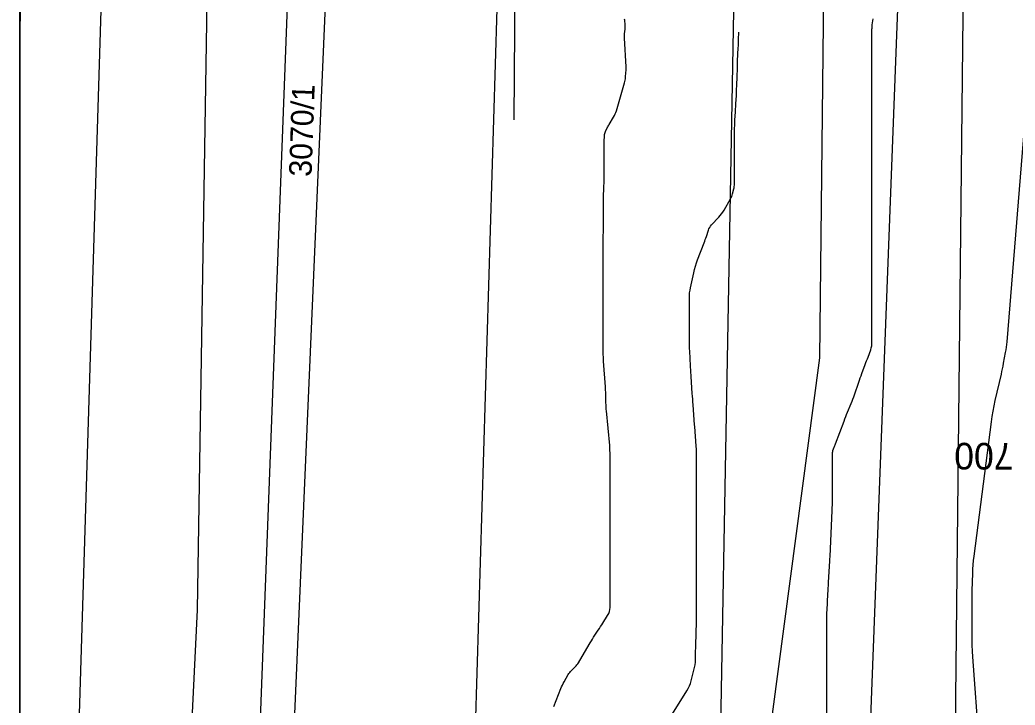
# Model space of a CAD drawing. Extents: x -534410 to -534262, y -1190162 to -1189584.
# Drawn here: x -534410.13 to -534372.72, y -1189890.36 to -1189864.58 of the extents above; entities that cross this region are included whole.
import ezdxf

# ---------------------------------------------------------------- set-up
doc = ezdxf.new("R2010")
doc.units = 0
for name, color, linetype in [('30', 7, 'Continuous'), ('31', 7, 'Continuous'), ('_N_text', 7, 'Continuous'), ('_rámeček', 7, 'Continuous'), ('_rámeček_mřížka', 7, 'Continuous'), ('Hranice parcel', 7, 'Continuous'), ('Parcelní čísla', 7, 'Continuous')]:
    doc.layers.add(name, color=color, linetype=linetype)

msp = doc.modelspace()

# ---------------------------------------------------------------- linework, layer by layer
at = {"layer": '30'}
for points in [[(-534390.792, -1189830.764), (-534391.145, -1189834.263), (-534391.226, -1189835.167), (-534391.285, -1189836.071), (-534391.324, -1189836.977), (-534391.341, -1189837.885), (-534391.562, -1189868.34)], [(-534374.066, -1189891.779), (-534374.31, -1189888.535), (-534374.324, -1189888.32), (-534374.334, -1189888.104), (-534374.339, -1189887.887), (-534374.341, -1189887.671), (-534374.338, -1189886.697), (-534374.337, -1189886.535), (-534374.335, -1189886.373), (-534374.332, -1189886.21), (-534374.329, -1189886.048), (-534374.312, -1189885.399), (-534374.306, -1189885.237), (-534374.295, -1189885.075), (-534374.281, -1189884.913), (-534374.262, -1189884.752), (-534373.614, -1189879.703), (-534373.585, -1189879.5), (-534373.551, -1189879.298), (-534373.513, -1189879.097), (-534373.469, -1189878.897), (-534373.238, -1189877.899), (-534373.215, -1189877.799), (-534373.194, -1189877.698), (-534373.173, -1189877.598), (-534373.153, -1189877.497), (-534373.077, -1189877.095), (-534373.059, -1189876.994), (-534373.044, -1189876.892), (-534373.032, -1189876.791), (-534373.022, -1189876.689), (-534371.559, -1189858.553)], [(-534385.597, -1189890.68), (-534385.058, -1189889.813), (-534385.007, -1189889.724), (-534384.963, -1189889.632), (-534384.926, -1189889.538), (-534384.896, -1189889.44), (-534384.791, -1189889.043), (-534384.767, -1189888.943), (-534384.75, -1189888.843), (-534384.738, -1189888.741), (-534384.733, -1189888.639), (-534384.715, -1189887.888), (-534384.714, -1189887.866), (-534384.714, -1189887.823), (-534384.714, -1189887.801), (-534384.698, -1189887.082), (-534384.695, -1189886.963), (-534384.693, -1189886.844), (-534384.692, -1189886.726), (-534384.692, -1189886.607), (-534384.692, -1189881.082), (-534384.693, -1189880.963), (-534384.696, -1189880.845), (-534384.702, -1189880.726), (-534384.71, -1189880.608), (-534384.764, -1189879.872), (-534384.769, -1189879.808), (-534384.824, -1189879.057), (-534384.832, -1189878.951), (-534384.839, -1189878.844), (-534384.847, -1189878.738), (-534384.853, -1189878.632), (-534384.893, -1189877.994), (-534384.917, -1189877.596), (-534384.952, -1189877.039), (-534384.957, -1189876.942), (-534384.961, -1189876.844), (-534384.963, -1189876.747), (-534384.964, -1189876.65), (-534384.964, -1189876.12), (-534384.964, -1189875.955), (-534384.964, -1189875.624), (-534384.964, -1189875.514), (-534384.964, -1189875.039), (-534384.961, -1189874.942), (-534384.953, -1189874.846), (-534384.94, -1189874.75), (-534384.922, -1189874.654), (-534384.801, -1189874.092), (-534384.772, -1189873.967), (-534384.737, -1189873.844), (-534384.698, -1189873.722), (-534384.655, -1189873.601), (-534384.407, -1189872.959), (-534384.386, -1189872.902), (-534384.365, -1189872.844), (-534384.345, -1189872.786), (-534384.325, -1189872.727), (-534384.25, -1189872.493), (-534384.228, -1189872.436), (-534384.2, -1189872.382), (-534384.167, -1189872.332), (-534384.127, -1189872.286), (-534383.86, -1189872.004), (-534383.804, -1189871.941), (-534383.751, -1189871.874), (-534383.703, -1189871.805), (-534383.659, -1189871.732), (-534383.416, -1189871.304), (-534383.393, -1189871.261), (-534383.374, -1189871.217), (-534383.357, -1189871.172), (-534383.344, -1189871.126), (-534383.296, -1189870.938), (-534383.285, -1189870.891), (-534383.278, -1189870.844), (-534383.273, -1189870.796), (-534383.272, -1189870.748), (-534383.272, -1189868.967), (-534383.271, -1189868.906), (-534383.271, -1189868.845), (-534383.269, -1189868.783), (-534383.267, -1189868.722), (-534383.259, -1189868.478), (-534383.257, -1189868.417), (-534383.254, -1189868.356), (-534383.251, -1189868.295), (-534383.247, -1189868.234), (-534383.2, -1189867.534), (-534383.196, -1189867.465), (-534383.192, -1189867.396), (-534383.189, -1189867.327), (-534383.187, -1189867.258), (-534383.178, -1189866.983), (-534383.176, -1189866.913), (-534383.173, -1189866.844), (-534383.171, -1189866.775), (-534383.17, -1189866.706), (-534383.161, -1189866.405), (-534383.159, -1189866.332), (-534383.157, -1189866.259), (-534383.153, -1189866.186), (-534383.15, -1189866.113), (-534383.124, -1189865.628), (-534383.12, -1189865.55), (-534383.117, -1189865.471), (-534383.114, -1189865.393), (-534383.112, -1189865.315), (-534383.105, -1189865.034)]]:
    msp.add_lwpolyline(points, dxfattribs=at)
at = {"layer": '31'}
for points in [[(-534390.056, -1189890.413), (-534389.793, -1189889.733), (-534389.767, -1189889.668), (-534389.738, -1189889.605), (-534389.707, -1189889.543), (-534389.674, -1189889.483), (-534389.516, -1189889.207), (-534389.49, -1189889.165), (-534389.461, -1189889.125), (-534389.43, -1189889.088), (-534389.396, -1189889.052), (-534389.254, -1189888.914), (-534389.22, -1189888.878), (-534389.188, -1189888.84), (-534389.159, -1189888.801), (-534389.133, -1189888.759), (-534388.73, -1189888.076), (-534388.689, -1189888.008), (-534388.647, -1189887.94), (-534388.605, -1189887.872), (-534388.562, -1189887.805), (-534388.388, -1189887.537), (-534388.345, -1189887.47), (-534388.302, -1189887.402), (-534388.259, -1189887.335), (-534388.216, -1189887.268), (-534388.036, -1189886.984), (-534387.997, -1189886.913), (-534387.969, -1189886.838), (-534387.953, -1189886.76), (-534387.947, -1189886.679), (-534387.947, -1189880.897), (-534387.947, -1189880.871), (-534387.947, -1189880.845), (-534387.948, -1189880.818), (-534387.949, -1189880.792), (-534387.952, -1189880.687), (-534387.953, -1189880.66), (-534387.955, -1189880.634), (-534387.956, -1189880.608), (-534387.959, -1189880.582), (-534388.085, -1189879.282), (-534388.089, -1189879.238), (-534388.092, -1189879.194), (-534388.094, -1189879.151), (-534388.096, -1189879.107), (-534388.101, -1189878.932), (-534388.102, -1189878.888), (-534388.103, -1189878.844), (-534388.104, -1189878.801), (-534388.105, -1189878.757), (-534388.109, -1189878.568), (-534388.111, -1189878.522), (-534388.113, -1189878.476), (-534388.115, -1189878.43), (-534388.118, -1189878.384), (-534388.188, -1189877.411), (-534388.192, -1189877.354), (-534388.195, -1189877.298), (-534388.197, -1189877.241), (-534388.199, -1189877.184), (-534388.203, -1189876.958), (-534388.205, -1189876.901), (-534388.205, -1189876.844), (-534388.206, -1189876.788), (-534388.206, -1189876.731), (-534388.206, -1189872.956), (-534388.206, -1189872.9), (-534388.205, -1189872.845), (-534388.204, -1189872.789), (-534388.202, -1189872.733), (-534388.194, -1189872.509), (-534388.192, -1189872.454), (-534388.191, -1189872.398), (-534388.19, -1189872.342), (-534388.19, -1189872.286), (-534388.19, -1189871.403), (-534388.19, -1189871.347), (-534388.189, -1189871.291), (-534388.188, -1189871.235), (-534388.186, -1189871.18), (-534388.179, -1189870.95), (-534388.177, -1189870.897), (-534388.175, -1189870.844), (-534388.174, -1189870.792), (-534388.172, -1189870.739), (-534388.166, -1189870.529), (-534388.165, -1189870.477), (-534388.164, -1189870.424), (-534388.163, -1189870.372), (-534388.163, -1189870.319), (-534388.163, -1189869.37), (-534388.163, -1189869.317), (-534388.163, -1189869.265), (-534388.162, -1189869.212), (-534388.161, -1189869.16), (-534388.154, -1189868.921), (-534388.151, -1189868.883), (-534388.144, -1189868.847), (-534388.133, -1189868.811), (-534388.118, -1189868.776), (-534388.05, -1189868.64), (-534388.032, -1189868.606), (-534388.014, -1189868.573), (-534387.996, -1189868.54), (-534387.976, -1189868.507), (-534387.811, -1189868.233), (-534387.779, -1189868.176), (-534387.751, -1189868.116), (-534387.727, -1189868.056), (-534387.706, -1189867.993), (-534387.4, -1189866.942), (-534387.387, -1189866.893), (-534387.377, -1189866.844), (-534387.369, -1189866.794), (-534387.363, -1189866.743), (-534387.347, -1189866.541), (-534387.343, -1189866.49), (-534387.342, -1189866.44), (-534387.342, -1189866.389), (-534387.344, -1189866.338), (-534387.403, -1189865.264), (-534387.404, -1189865.222), (-534387.404, -1189865.18), (-534387.402, -1189865.138), (-534387.398, -1189865.096), (-534387.38, -1189864.928), (-534387.376, -1189864.886), (-534387.375, -1189864.844), (-534387.375, -1189864.802), (-534387.377, -1189864.76), (-534387.392, -1189864.586), (-534387.396, -1189864.543)], [(-534379.798, -1189892.822), (-534379.798, -1189886.856), (-534379.798, -1189886.85), (-534379.797, -1189886.845), (-534379.796, -1189886.839), (-534379.795, -1189886.834), (-534379.789, -1189886.812), (-534379.788, -1189886.807), (-534379.787, -1189886.802), (-534379.786, -1189886.796), (-534379.785, -1189886.79), (-534379.754, -1189886.167), (-534379.748, -1189886.061), (-534379.743, -1189885.955), (-534379.737, -1189885.849), (-534379.731, -1189885.744), (-534379.682, -1189884.923), (-534379.681, -1189884.907), (-534379.68, -1189884.891), (-534379.679, -1189884.844), (-534379.677, -1189884.787), (-534379.677, -1189884.77), (-534379.676, -1189884.762), (-534379.595, -1189883.032), (-534379.594, -1189883.013), (-534379.594, -1189882.994), (-534379.593, -1189882.975), (-534379.593, -1189882.957), (-534379.591, -1189882.882), (-534379.59, -1189882.863), (-534379.59, -1189882.844), (-534379.59, -1189882.826), (-534379.59, -1189882.807), (-534379.59, -1189880.912), (-534379.588, -1189880.878), (-534379.584, -1189880.846), (-534379.576, -1189880.813), (-534379.566, -1189880.782), (-534379.517, -1189880.657), (-534379.505, -1189880.625), (-534379.493, -1189880.594), (-534379.481, -1189880.562), (-534379.469, -1189880.531), (-534379.148, -1189879.667), (-534379.117, -1189879.584), (-534379.085, -1189879.502), (-534379.053, -1189879.419), (-534379.019, -1189879.337), (-534378.884, -1189879.009), (-534378.851, -1189878.926), (-534378.819, -1189878.844), (-534378.788, -1189878.76), (-534378.759, -1189878.677), (-534378.598, -1189878.208), (-534378.57, -1189878.127), (-534378.541, -1189878.046), (-534378.512, -1189877.965), (-534378.482, -1189877.884), (-534378.353, -1189877.54), (-534378.327, -1189877.471), (-534378.301, -1189877.402), (-534378.275, -1189877.332), (-534378.25, -1189877.262), (-534378.15, -1189876.984), (-534378.128, -1189876.914), (-534378.112, -1189876.842), (-534378.103, -1189876.77), (-534378.1, -1189876.696), (-534378.1, -1189864.923), (-534378.099, -1189864.884), (-534378.097, -1189864.845), (-534378.093, -1189864.806), (-534378.088, -1189864.767), (-534378.053, -1189864.535)]]:
    msp.add_lwpolyline(points, dxfattribs=at)
at = {"layer": '_rámeček'}
msp.add_line((-534410.126, -1189584.47), (-534410.126, -1190161.97), dxfattribs=at)
msp.add_lwpolyline([(-534410.126, -1189794.47), (-534261.626, -1189794.47), (-534261.626, -1189899.47), (-534410.126, -1189899.47)], close=True, dxfattribs=at)
at = {"layer": '_rámeček_mřížka'}
msp.add_line((-534410.126, -1189584.47), (-534410.126, -1190161.97), dxfattribs=at)
at = {"layer": 'Hranice parcel'}
for p, q in [((-534410.126, -1189865.16), (-534408.06, -1189801.17)), ((-534403.19, -1189945.91), (-534398.3, -1189817.87))]:
    msp.add_line(p, q, dxfattribs=at)
for points in [[(-534395.93, -1189955.06), (-534393.76, -1189916.2), (-534389.49, -1189774.63), (-534390.92, -1189749.37)], [(-534385.61, -1189919.11), (-534380.06, -1189877.29), (-534378.67, -1189750.28)], [(-534385.61, -1189919.11), (-534383.81, -1189892.54), (-534382.22, -1189804.86), (-534381.85, -1189775.86), (-534383.09, -1189750.44)], [(-534383.94, -1189956.8), (-534379.19, -1189918.48), (-534376.74, -1189853.94), (-534375.92, -1189797.44), (-534376.41, -1189774.02), (-534378.12, -1189750.26)], [(-534406.13, -1189942), (-534403.45, -1189886.77), (-534402.68, -1189837.82), (-534401.95, -1189776.76), (-534406.3, -1189754), (-534406.48, -1189752.31)], [(-534373.61, -1189764.09), (-534375.04, -1189897.07), (-534384.28, -1189963.65)], [(-534410.126, -1189932.794), (-534408.16, -1189899.66), (-534406.57, -1189847.9), (-534405.68, -1189781.38), (-534406.95, -1189766.9)], [(-534403.19, -1189945.91), (-534400.52, -1189907.49), (-534398.39, -1189858.23), (-534398.3, -1189817.87)]]:
    msp.add_lwpolyline(points, dxfattribs=at)

# ---------------------------------------------------------------- texts
at = {"layer": '_N_text'}
msp.add_text('700', height=1, rotation=179.8487, dxfattribs=at).set_placement((-534372.778, -1189880.493))
at = {"layer": 'Parcelní čísla'}
msp.add_text('3070/1', height=0.85, rotation=88, dxfattribs=at).set_placement((-534399.165, -1189870.486))

doc.saveas('drawing.dxf')
